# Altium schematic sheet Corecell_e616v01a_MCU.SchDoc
size B; DrawnBy: Erik Fountain; DocumentNumber: 3; SheetNumber: 3; SheetTotal: 5; PageSetup: Record=PageOptions¦CenterHorizontal=True¦CenterVertical=True¦PrintScale=0.72¦XCorrection=1.00¦YCorrection=1.00¦PrintKind=0¦BorderSize=5000000¦LeftOffset=0¦BottomOffset=0¦Orientation=2¦PaperLength=1000¦PaperWidth=1000¦Scale=100¦PaperSource=7¦PrintQuality=-4¦MediaType=1¦DitherType=10¦PaperKind=Letter¦PrintScaleMode=1
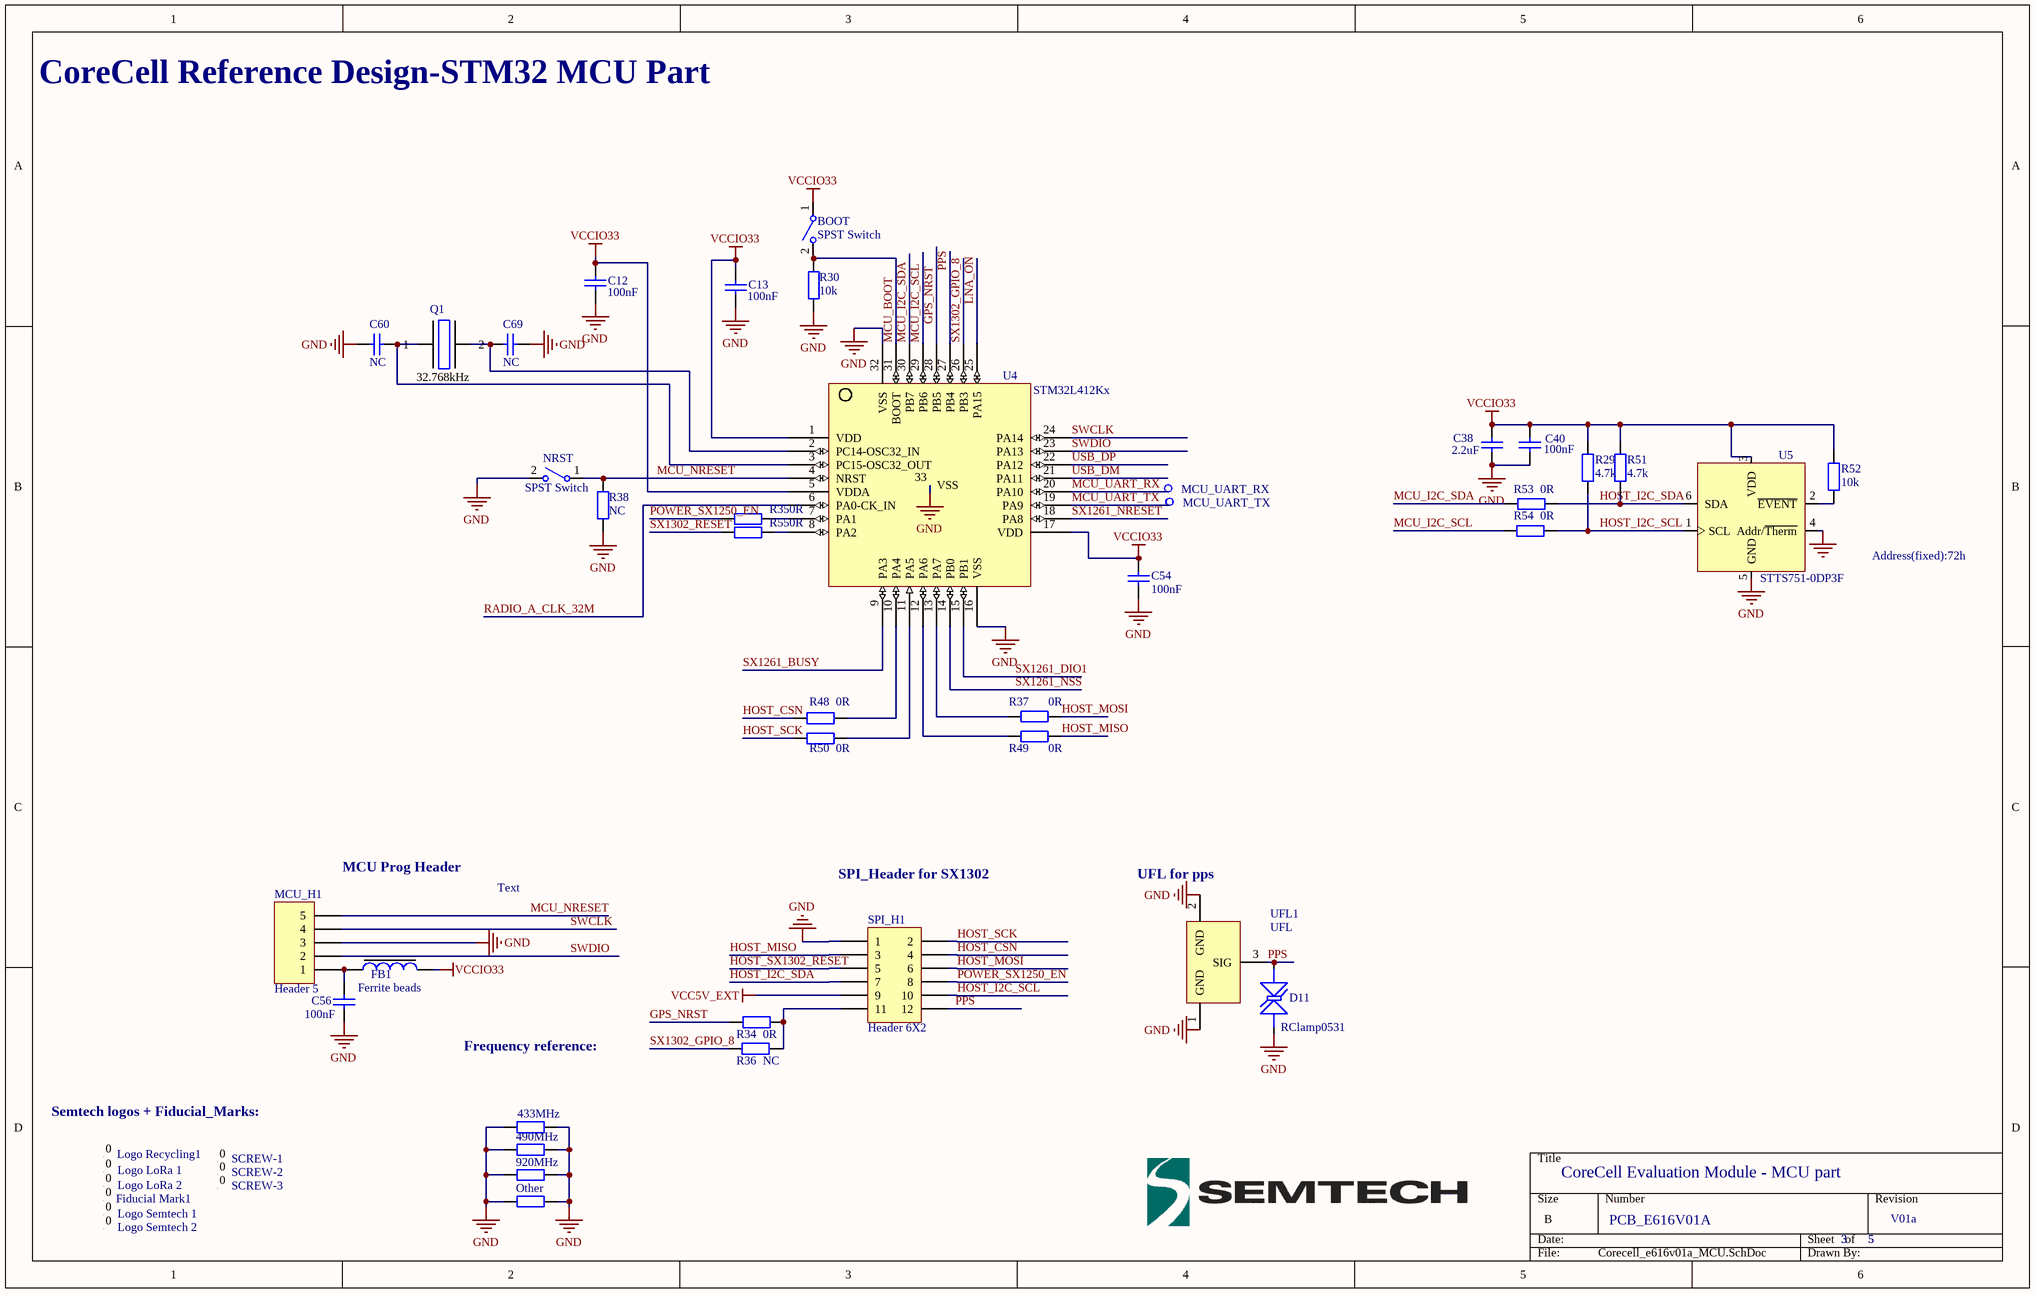
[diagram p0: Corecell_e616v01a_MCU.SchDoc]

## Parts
433MHz  Resistor  [rlc_402_smd_small]  (value not drawn)
490MHz  Resistor  [rlc_402_smd_small]  (value not drawn)
920MHz  Resistor  [rlc_402_smd_small]  (value not drawn)
BOOT  SPST Switch  [tackle_3*3mm]
C12  value 100nF  [rlc_201_smd_small]  (hidden comment: Cap)
C13  value 100nF  [rlc_201_smd_small]  (hidden comment: Cap)
C38  value 2.2uF  [rlc_201_smd_small]  (hidden comment: Cap)
C40  value 100nF  [rlc_201_smd_small]  (hidden comment: Cap)
C54  value 100nF  [rlc_201_smd_small]  (hidden comment: Cap)
C56  value 100nF  [rlc_402_smd_small]  (hidden comment: Cap)
C60  value NC  [rlc_201_smd_small]  (hidden comment: Cap)
C69  value NC  [rlc_201_smd_small]  (hidden comment: Cap)
D11  RClamp0531  [SLP1006P2T]
FB1  Ferrite beads  [rlc_402_smd_small]
Fiducial_Mark1  Logo symbol  BOT  [fiducial_mark_signal_top]  (value not drawn)
Logo_LoRa_1  Logo symbol Bot  [Logo LoRa Size2]  (value not drawn)
Logo_LoRa_2  Logo symbol TOP  [Logo LoRa Size3]  (value not drawn)
Logo_Recycling1  Logo symbol  [Logo Recycling1]  (value not drawn)
Logo_Semtech_1  Logo symbol TOP  [logo_semtech_horiz_size3]  (value not drawn)
Logo_Semtech_2  Logo Semtech  Bot2  [logo_semtech_horiz_size2]  (value not drawn)
MCU_H1  Header 5  [ProgPad]
MCU_UART_RX  Test Pin  [PIN_SMD]  (value not drawn)
MCU_UART_TX  Test Pin  [PIN_SMD]  (value not drawn)
NRST  SPST Switch  [tackle_3*3mm]
Other  Resistor  [rlc_402_smd_small]  (value not drawn)
Q1  value 32.768kHz  [XTAL_3215_SMD]  (hidden comment: 3215)
R29  value 4.7k  [rlc_201_smd_small]  (hidden comment: Resistor)
R30  value 10k  [rlc_201_smd_small]  (hidden comment: Resistor)
R34  value 0R  [rlc_201_smd_small]  (hidden comment: Resistor)
R35  value 0R  [rlc_201_smd_small]  (hidden comment: Resistor)
R36  value NC  [rlc_201_smd_small]  (hidden comment: Resistor)
R37  value 0R  [rlc_201_smd_small]  (hidden comment: Resistor)
R38  value NC  [rlc_201_smd_small]  (hidden comment: Resistor)
R48  value 0R  [rlc_201_smd_small]  (hidden comment: Resistor)
R49  value 0R  [rlc_201_smd_small]  (hidden comment: Resistor)
R50  value 0R  [rlc_201_smd_small]  (hidden comment: Resistor)
R51  value 4.7k  [rlc_201_smd_small]  (hidden comment: Resistor)
R52  value 10k  [rlc_201_smd_small]  (hidden comment: Resistor)
R53  value 0R  [rlc_201_smd_small]  (hidden comment: Resistor)
R54  value 0R  [rlc_201_smd_small]  (hidden comment: Resistor)
R55  value 0R  [rlc_201_smd_small]  (hidden comment: Resistor)
SCREW-1  Logo symbol  [screw-M3]  (value not drawn)
SCREW-2  Logo symbol  [SCREW-M3]  (value not drawn)
SCREW-3  Logo symbol  [SCREW-M3]  (value not drawn)
SPI_H1  Header 6X2  [header_6_2_2.0]
U4  STM32L412Kx  [UFQFPN32_5x5mm]
U5  STTS751-0DP3F  [UDFN-6L_2X2mm]
UFL1  UFL  [UFL]

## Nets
GND: 433MHz.1 433MHz.2 490MHz.1 490MHz.2 920MHz.1 920MHz.2 C12.1 C13.1 C38.2 C40.2 C54.1 C56.1 C60.2 C69.1 D11.2(K) MCU_H1.3 NRST.2(NO) Other.1 Other.2 R30.1 R38.2 SPI_H1.1 U4.16(VSS) U4.32(VSS) U4.33(VSS) U5.4(Addr/~{Therm}) U5.5(GND) UFL1.1(GND) UFL1.2(GND)
VCC5V_EXT: SPI_H1.9
VCCIO33: BOOT.1(COMMON) C12.2 C13.2 C38.1 C40.1 C54.2 FB1.2 R29.2 R51.2 R52.2 U4.1(VDD) U4.5(VDDA) U4.17(VDD) U5.3(VDD)
GPS_NRST: R34.2 U4.28(PB5)
HOST_CSN: R48.2 SPI_H1.4
HOST_I2C_SCL: R29.1 R54.2 SPI_H1.10 U5.1(SCL)
HOST_I2C_SDA: R51.1 R53.2 SPI_H1.7 U5.6(SDA)
HOST_MISO: R49.1 SPI_H1.3
HOST_MOSI: R37.1 SPI_H1.6
HOST_SCK: R50.2 SPI_H1.2
HOST_SX1302_RESET: SPI_H1.5
LNA_ON: U4.25(PA15)
MCU_BOOT: BOOT.2(NO) R30.2 U4.31(BOOT)
MCU_I2C_SCL: R54.1 U4.29(PB6)
MCU_I2C_SDA: R53.1 U4.30(PB7)
MCU_NRESET: MCU_H1.5 NRST.1(COMMON) R38.1 U4.4(NRST)
MCU_UART_RX: MCU_UART_RX.1(pin) U4.20(PA10)
MCU_UART_TX: MCU_UART_TX.1(pin) U4.19(PA9)
POWER_SX1250_EN: R55.2 SPI_H1.8
PPS: D11.1(A) SPI_H1.12 U4.27(PB4) UFL1.3(SIG)
RADIO_A_CLK_32M: U4.6(PA0-CK_IN)
SWCLK: MCU_H1.4 U4.24(PA14)
SWDIO: MCU_H1.2 U4.23(PA13)
SX1261_BUSY: U4.9(PA3)
SX1261_DIO1: U4.15(PB1)
SX1261_NRESET: U4.18(PA8)
SX1261_NSS: U4.14(PB0)
SX1302_GPIO_8: R36.2 U4.26(PB3)
SX1302_RESET: R35.2
USB_DM: U4.21(PA11)
USB_DP: U4.22(PA12)
NetC56_2: C56.2 FB1.1 MCU_H1.1
NetC60_1: C60.1 Q1.1 U4.3(PC15-OSC32_OUT)
NetC69_2: C69.2 Q1.2 U4.2(PC14-OSC32_IN)
NetR34_1: R34.1 R36.1 SPI_H1.11
NetR35_1: R35.1 U4.8(PA2)
NetR37_2: R37.2 U4.13(PA7)
NetR48_1: R48.1 U4.10(PA4)
NetR49_2: R49.2 U4.12(PA6)
NetR50_1: R50.1 U4.11(PA5)
NetR52_1: R52.1 U5.2(~{EVENT})
NetR55_1: R55.1 U4.7(PA1)

Not connected (* = marked no-connect by the designer): Fiducial_Mark1 0; Logo_LoRa_1 0; Logo_LoRa_2 0; Logo_Recycling1 0; Logo_Semtech_1 0; Logo_Semtech_2 0; SCREW-1 0; SCREW-2 0; SCREW-3 0

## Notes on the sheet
- CoreCell Reference Design-STM32 MCU Part
- Address(fixed):72h
- (near MCU_H1) MCU Prog Header
- Text
- SPI_Header for SX1302
- (near UFL1) UFL for pps
- Frequency reference:
- Semtech logos + Fiducial_Marks:
- CoreCell Evaluation Module - MCU part
- PCB_E616V01A
- V01a

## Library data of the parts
433MHz 920MHz Other = Resistor: Resistor SMD - IEC symbol version; Value: NC
490MHz = Resistor: Resistor SMD - IEC symbol version; Value: 0R
BOOT NRST = SW-SPST: SPST, N.O. - Tactile Switch; Value: SW_3_3_1.5
C12 C13 C38 C40 C54 C56 C60 C69 = Cap: Capacitor SMD
D11 = RClamp0531T: Ultra Low Capacitance 1-line ESD Protection
FB1 = Ferrite beads: Value: 10R @100MHz
Fiducial_Mark1 Logo_LoRa_1 Logo_LoRa_2 Logo_Recycling1 Logo_Semtech_1 Logo_Semtech_2 SCREW-1-SCREW-3 = Logo: Schematic symbol for Logo
MCU_H1 = Header 5: Header, 5-Pin; Value: NC
MCU_UART_RX MCU_UART_TX = test_pin
Q1 = Xtal: Crystal oscillator
R29 R30 R34-R38 R48-R55 = Resistor: Resistor SMD - IEC symbol version
SPI_H1 = Header 6X2: Header, 12-Pin, Dual row; Value: NC
U4 = STM32L412Kx: Ultra-low-power Arm® Cortex®-M4 32-bit MCU+FPU, 100DMIPS, up to 128KB Flash, 40KB SRAM, analog, ext. SMPS; Value: STM32L412KBU6
U5 = STTS751: 2.25 V low-voltage local digital temperature sensor
UFL1 = UFL: UFL connector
